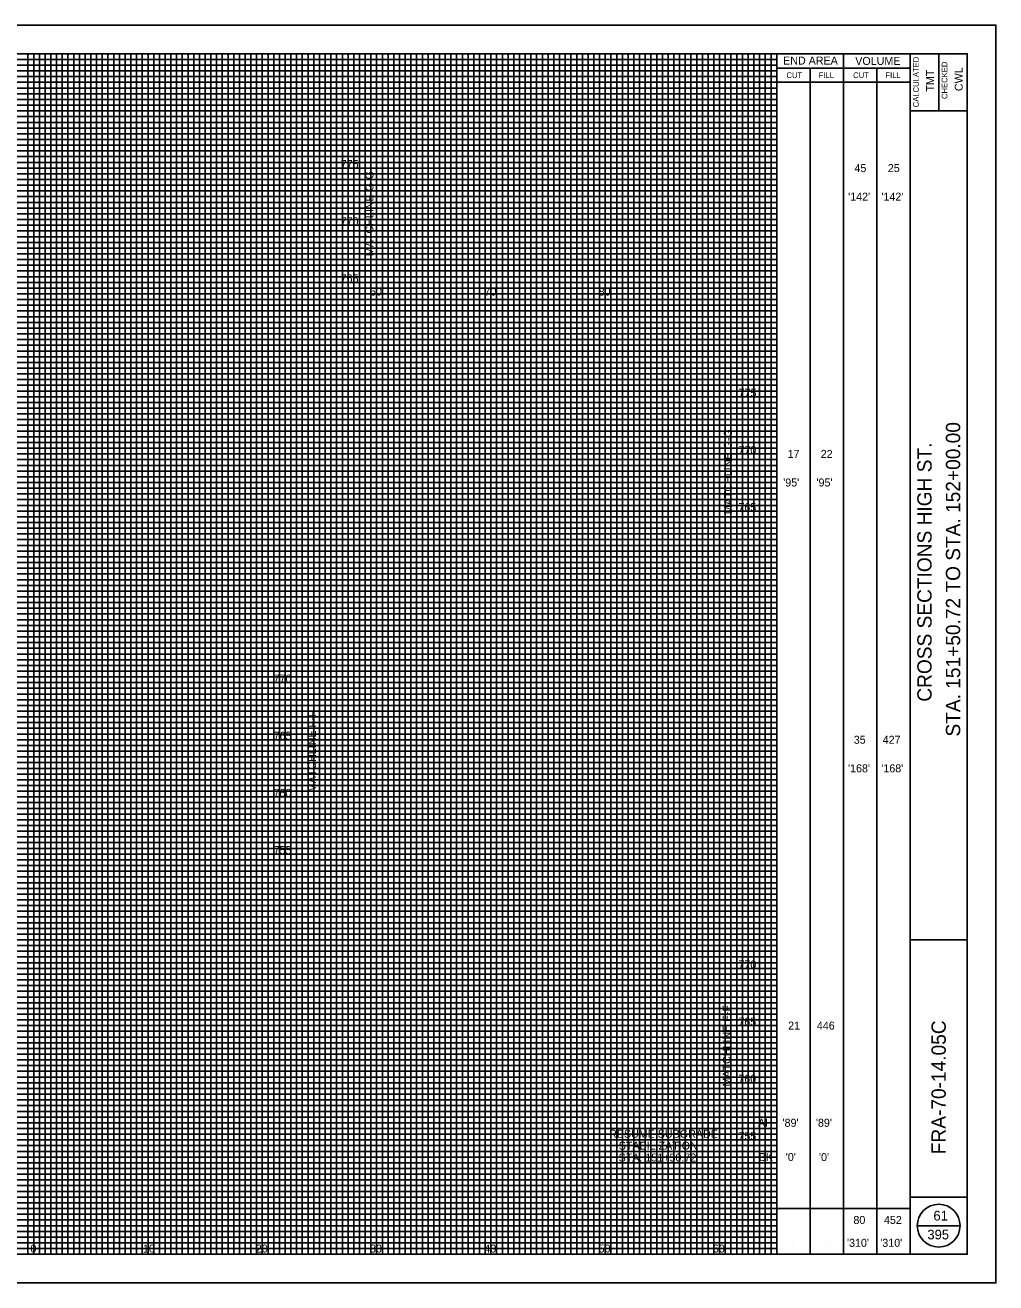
# Model space of a CAD drawing. Extents: x -10 to 160, y -2 to 568.
# Drawn here: x 75.1 to 160, y 342.5 to 452.5 of the extents above; entities that cross this region are included whole.
import ezdxf

# ---------------------------------------------------------------- set-up
doc = ezdxf.new("R2010")
doc.units = 0
for name, color, linetype in [('DR_P_Text', 7, 'Continuous'), ('SV_X_Text_Comment', 7, 'Continuous'), ('SV_X_Text_Elevation', 7, 'Continuous'), ('XS_P_Annotation', 7, 'Continuous'), ('XS_P_Finished_Grade', 7, 'Continuous'), ('XS_P_Subgrade', 7, 'Continuous'), ('XS_P_Text_MarkedPoint', 7, 'Continuous')]:
    doc.layers.add(name, color=color, linetype=linetype)

msp = doc.modelspace()

# ---------------------------------------------------------------- linework, layer by layer
at = {"layer": 'SV_X_Text_Comment'}
msp.add_lwpolyline([(-10, 342.5), (160, 342.5), (160, 452.5), (-10, 452.5)], close=True, dxfattribs=at)
at = {"layer": 'SV_X_Text_Elevation'}
for p, q in [((75.33, 345), (75.33, 450)), ((76.33, 345), (76.33, 450)), ((76.83, 345), (76.83, 450)), ((77.33, 345), (77.33, 450)), ((77.83, 345), (77.83, 450)), ((78.33, 345), (78.33, 450)), ((78.83, 345), (78.83, 450)), ((79.33, 345), (79.33, 450)), ((79.83, 345), (79.83, 450)), ((80.33, 345), (80.33, 450)), ((81.33, 345), (81.33, 450)), ((81.83, 345), (81.83, 450)), ((82.33, 345), (82.33, 450)), ((82.83, 345), (82.83, 450)), ((83.33, 345), (83.33, 450)), ((83.83, 345), (83.83, 450)), ((84.33, 345), (84.33, 450)), ((84.83, 345), (84.83, 450)), ((85.33, 345), (85.33, 450)), ((86.33, 345), (86.33, 450)), ((86.83, 345), (86.83, 450)), ((87.33, 345), (87.33, 450)), ((87.83, 345), (87.83, 450)), ((88.33, 345), (88.33, 450)), ((88.83, 345), (88.83, 450)), ((89.33, 345), (89.33, 450)), ((89.83, 345), (89.83, 450)), ((90.33, 345), (90.33, 450)), ((91.33, 345), (91.33, 450)), ((91.83, 345), (91.83, 450)), ((92.33, 345), (92.33, 450)), ((92.83, 345), (92.83, 450)), ((93.33, 345), (93.33, 450)), ((93.83, 345), (93.83, 450)), ((94.33, 345), (94.33, 450)), ((94.83, 345), (94.83, 450)), ((95.33, 345), (95.33, 450)), ((96.33, 345), (96.33, 450)), ((96.83, 345), (96.83, 450)), ((97.33, 345), (97.33, 450)), ((97.83, 345), (97.83, 450)), ((98.33, 345), (98.33, 450)), ((98.83, 345), (98.83, 450)), ((99.33, 345), (99.33, 450)), ((99.83, 345), (99.83, 450)), ((100.33, 345), (100.33, 450)), ((101.33, 345), (101.33, 450)), ((101.83, 345), (101.83, 450)), ((102.33, 345), (102.33, 450)), ((102.83, 345), (102.83, 450)), ((103.33, 345), (103.33, 450)), ((103.83, 345), (103.83, 450)), ((104.33, 345), (104.33, 450)), ((104.83, 345), (104.83, 450)), ((105.33, 345), (105.33, 450)), ((106.33, 345), (106.33, 450)), ((106.83, 345), (106.83, 450)), ((107.33, 345), (107.33, 450)), ((107.83, 345), (107.83, 450)), ((108.33, 345), (108.33, 450)), ((108.83, 345), (108.83, 450)), ((109.33, 345), (109.33, 450)), ((109.83, 345), (109.83, 450)), ((110.33, 345), (110.33, 450)), ((111.33, 345), (111.33, 450)), ((111.83, 345), (111.83, 450)), ((112.33, 345), (112.33, 450)), ((112.83, 345), (112.83, 450)), ((113.33, 345), (113.33, 450)), ((113.83, 345), (113.83, 450)), ((114.33, 345), (114.33, 450)), ((114.83, 345), (114.83, 450)), ((115.33, 345), (115.33, 450)), ((116.33, 345), (116.33, 450)), ((116.83, 345), (116.83, 450)), ((117.33, 345), (117.33, 450)), ((117.83, 345), (117.83, 450)), ((118.33, 345), (118.33, 450)), ((118.83, 345), (118.83, 450)), ((119.33, 345), (119.33, 450)), ((119.83, 345), (119.83, 450)), ((120.33, 345), (120.33, 450)), ((121.33, 345), (121.33, 450)), ((121.83, 345), (121.83, 450)), ((122.33, 345), (122.33, 450)), ((122.83, 345), (122.83, 450)), ((123.33, 345), (123.33, 450)), ((123.83, 345), (123.83, 450)), ((124.33, 345), (124.33, 450)), ((124.83, 345), (124.83, 450)), ((125.33, 345), (125.33, 450)), ((126.33, 345), (126.33, 450)), ((126.83, 345), (126.83, 450)), ((127.33, 345), (127.33, 450)), ((127.83, 345), (127.83, 450)), ((128.33, 345), (128.33, 450)), ((128.83, 345), (128.83, 450)), ((129.33, 345), (129.33, 450)), ((129.83, 345), (129.83, 450)), ((130.33, 345), (130.33, 450)), ((131.33, 345), (131.33, 450)), ((131.83, 345), (131.83, 450)), ((132.33, 345), (132.33, 450)), ((132.83, 345), (132.83, 450)), ((133.33, 345), (133.33, 450)), ((133.83, 345), (133.83, 450)), ((134.33, 345), (134.33, 450)), ((134.83, 345), (134.83, 450)), ((135.33, 345), (135.33, 450)), ((136.33, 345), (136.33, 450)), ((136.83, 345), (136.83, 450)), ((137.33, 345), (137.33, 450)), ((137.83, 345), (137.83, 450)), ((138.33, 345), (138.33, 450)), ((138.83, 345), (138.83, 450)), ((139.33, 345), (139.33, 450)), ((139.83, 345), (139.83, 450)), ((140.33, 345), (140.33, 450)), ((5.83, 449.5), (140.83, 449.5)), ((5.83, 449), (140.83, 449)), ((5.83, 448.5), (140.83, 448.5)), ((5.83, 448), (140.83, 448)), ((5.83, 447.5), (140.83, 447.5)), ((5.83, 447), (140.83, 447)), ((5.83, 446.5), (140.83, 446.5)), ((5.83, 446), (140.83, 446)), ((5.83, 445.5), (140.83, 445.5)), ((5.83, 444.5), (140.83, 444.5)), ((5.83, 444), (140.83, 444)), ((5.83, 443.5), (140.83, 443.5)), ((5.83, 443), (140.83, 443)), ((5.83, 442.5), (140.83, 442.5)), ((5.83, 442), (140.83, 442)), ((5.83, 441.5), (140.83, 441.5)), ((5.83, 441), (140.83, 441)), ((5.83, 440.5), (140.83, 440.5)), ((5.83, 439.5), (140.83, 439.5)), ((5.83, 439), (140.83, 439)), ((5.83, 438.5), (140.83, 438.5)), ((5.83, 438), (140.83, 438)), ((5.83, 437.5), (140.83, 437.5)), ((5.83, 437), (140.83, 437)), ((5.83, 436.5), (140.83, 436.5)), ((5.83, 436), (140.83, 436)), ((5.83, 435.5), (140.83, 435.5)), ((5.83, 434.5), (140.83, 434.5)), ((5.83, 434), (140.83, 434)), ((5.83, 433.5), (140.83, 433.5)), ((5.83, 433), (140.83, 433)), ((5.83, 432.5), (140.83, 432.5)), ((5.83, 432), (140.83, 432)), ((5.83, 431.5), (140.83, 431.5)), ((5.83, 431), (140.83, 431)), ((5.83, 430.5), (140.83, 430.5)), ((5.83, 429.5), (140.83, 429.5)), ((5.83, 429), (140.83, 429)), ((5.83, 428.5), (140.83, 428.5)), ((5.83, 428), (140.83, 428)), ((5.83, 427.5), (140.83, 427.5)), ((5.83, 427), (140.83, 427)), ((5.83, 426.5), (140.83, 426.5)), ((5.83, 426), (140.83, 426)), ((5.83, 425.5), (140.83, 425.5)), ((5.83, 424.5), (140.83, 424.5)), ((5.83, 424), (140.83, 424)), ((5.83, 423.5), (140.83, 423.5)), ((5.83, 423), (140.83, 423)), ((5.83, 422.5), (140.83, 422.5)), ((5.83, 422), (140.83, 422)), ((5.83, 421.5), (140.83, 421.5)), ((5.83, 421), (140.83, 421)), ((5.83, 420.5), (140.83, 420.5)), ((5.83, 419.5), (140.83, 419.5)), ((5.83, 419), (140.83, 419)), ((5.83, 418.5), (140.83, 418.5)), ((5.83, 418), (140.83, 418)), ((5.83, 417.5), (140.83, 417.5)), ((5.83, 417), (140.83, 417)), ((5.83, 416.5), (140.83, 416.5)), ((5.83, 416), (140.83, 416)), ((5.83, 415.5), (140.83, 415.5)), ((5.83, 414.5), (140.83, 414.5)), ((5.83, 414), (140.83, 414)), ((5.83, 413.5), (140.83, 413.5)), ((5.83, 413), (140.83, 413)), ((5.83, 412.5), (140.83, 412.5)), ((5.83, 412), (140.83, 412)), ((5.83, 411.5), (140.83, 411.5)), ((5.83, 411), (140.83, 411)), ((5.83, 410.5), (140.83, 410.5)), ((5.83, 409.5), (140.83, 409.5)), ((5.83, 409), (140.83, 409)), ((5.83, 408.5), (140.83, 408.5)), ((5.83, 408), (140.83, 408)), ((5.83, 407.5), (140.83, 407.5)), ((5.83, 407), (140.83, 407)), ((5.83, 406.5), (140.83, 406.5)), ((5.83, 406), (140.83, 406)), ((5.83, 405.5), (140.83, 405.5)), ((5.83, 404.5), (140.83, 404.5)), ((5.83, 404), (140.83, 404)), ((5.83, 403.5), (140.83, 403.5)), ((5.83, 403), (140.83, 403)), ((5.83, 402.5), (140.83, 402.5)), ((5.83, 402), (140.83, 402)), ((5.83, 401.5), (140.83, 401.5)), ((5.83, 401), (140.83, 401)), ((5.83, 400.5), (140.83, 400.5)), ((5.83, 399.5), (140.83, 399.5)), ((5.83, 399), (140.83, 399)), ((5.83, 398.5), (140.83, 398.5)), ((5.83, 398), (140.83, 398)), ((5.83, 397.5), (140.83, 397.5)), ((5.83, 397), (140.83, 397)), ((5.83, 396.5), (140.83, 396.5)), ((5.83, 396), (140.83, 396)), ((5.83, 395.5), (140.83, 395.5)), ((5.83, 394.5), (140.83, 394.5)), ((5.83, 394), (140.83, 394)), ((5.83, 393.5), (140.83, 393.5)), ((5.83, 393), (140.83, 393)), ((5.83, 392.5), (140.83, 392.5)), ((5.83, 392), (140.83, 392)), ((5.83, 391.5), (140.83, 391.5)), ((5.83, 391), (140.83, 391)), ((5.83, 390.5), (140.83, 390.5)), ((5.83, 389.5), (140.83, 389.5)), ((5.83, 389), (140.83, 389)), ((5.83, 388.5), (140.83, 388.5)), ((5.83, 388), (140.83, 388)), ((5.83, 387.5), (140.83, 387.5)), ((5.83, 387), (140.83, 387)), ((5.83, 386.5), (140.83, 386.5)), ((5.83, 386), (140.83, 386)), ((5.83, 385.5), (140.83, 385.5)), ((5.83, 384.5), (140.83, 384.5)), ((5.83, 384), (140.83, 384)), ((5.83, 383.5), (140.83, 383.5)), ((5.83, 383), (140.83, 383)), ((5.83, 382.5), (140.83, 382.5)), ((5.83, 382), (140.83, 382)), ((5.83, 381.5), (140.83, 381.5)), ((5.83, 381), (140.83, 381)), ((5.83, 380.5), (140.83, 380.5)), ((5.83, 379.5), (140.83, 379.5)), ((5.83, 379), (140.83, 379)), ((5.83, 378.5), (140.83, 378.5)), ((5.83, 378), (140.83, 378)), ((5.83, 377.5), (140.83, 377.5)), ((5.83, 377), (140.83, 377)), ((5.83, 376.5), (140.83, 376.5)), ((5.83, 376), (140.83, 376)), ((5.83, 375.5), (140.83, 375.5)), ((5.83, 374.5), (140.83, 374.5)), ((5.83, 374), (140.83, 374)), ((5.83, 373.5), (140.83, 373.5)), ((5.83, 373), (140.83, 373)), ((5.83, 372.5), (140.83, 372.5)), ((5.83, 372), (140.83, 372)), ((5.83, 371.5), (140.83, 371.5)), ((5.83, 371), (140.83, 371)), ((5.83, 370.5), (140.83, 370.5)), ((5.83, 369.5), (140.83, 369.5)), ((5.83, 369), (140.83, 369)), ((5.83, 368.5), (140.83, 368.5)), ((5.83, 368), (140.83, 368)), ((5.83, 367.5), (140.83, 367.5)), ((5.83, 367), (140.83, 367)), ((5.83, 366.5), (140.83, 366.5)), ((5.83, 366), (140.83, 366)), ((5.83, 365.5), (140.83, 365.5)), ((5.83, 364.5), (140.83, 364.5)), ((5.83, 364), (140.83, 364)), ((5.83, 363.5), (140.83, 363.5)), ((5.83, 363), (140.83, 363)), ((5.83, 362.5), (140.83, 362.5)), ((5.83, 362), (140.83, 362)), ((5.83, 361.5), (140.83, 361.5)), ((5.83, 361), (140.83, 361)), ((5.83, 360.5), (140.83, 360.5)), ((5.83, 359.5), (140.83, 359.5)), ((5.83, 359), (140.83, 359)), ((5.83, 358.5), (140.83, 358.5)), ((5.83, 358), (140.83, 358)), ((5.83, 357.5), (140.83, 357.5)), ((5.83, 357), (140.83, 357)), ((5.83, 356.5), (140.83, 356.5)), ((5.83, 356), (140.83, 356)), ((5.83, 355.5), (140.83, 355.5)), ((5.83, 354.5), (140.83, 354.5)), ((5.83, 354), (140.83, 354)), ((5.83, 353.5), (140.83, 353.5)), ((5.83, 353), (140.83, 353)), ((5.83, 352.5), (140.83, 352.5)), ((5.83, 352), (140.83, 352)), ((5.83, 351.5), (140.83, 351.5)), ((5.83, 351), (140.83, 351)), ((5.83, 350.5), (140.83, 350.5)), ((5.83, 349.5), (140.83, 349.5)), ((5.83, 349), (140.83, 349)), ((5.83, 348.5), (140.83, 348.5)), ((5.83, 348), (140.83, 348)), ((5.83, 347.5), (140.83, 347.5)), ((5.83, 347), (140.83, 347)), ((5.83, 346.5), (140.83, 346.5)), ((5.83, 346), (140.83, 346)), ((5.83, 345.5), (140.83, 345.5))]:
    msp.add_line(p, q, dxfattribs=at)
at = {"layer": 'XS_P_Annotation'}
for p, q in [((152.5, 345), (152.5, 450)), ((155, 450), (155, 445)), ((152.5, 445), (157.5, 445)), ((152.5, 372.5), (157.5, 372.5)), ((152.5, 350), (157.5, 350))]:
    msp.add_line(p, q, dxfattribs=at)
msp.add_lwpolyline([(0, 450), (157.5, 450), (157.5, 345), (0, 345)], close=True, dxfattribs=at)
at = {"layer": 'XS_P_Finished_Grade'}
for p, q in [((140.83, 345), (140.83, 450)), ((146.67, 345), (146.67, 450)), ((140.83, 448.75), (152.5, 448.75)), ((143.75, 345), (143.75, 448.75)), ((149.58, 345), (149.58, 448.75)), ((140.83, 447.5), (152.5, 447.5)), ((140.83, 349), (152.5, 349)), ((153.12, 347.5), (156.88, 347.5)), ((142.29, 346), (142.29, 346)), ((145.21, 346), (145.21, 346)), ((148.12, 346), (148.12, 346)), ((151.04, 346), (151.04, 346))]:
    msp.add_line(p, q, dxfattribs=at)
msp.add_circle((155, 347.5), 1.87, dxfattribs=at)
at = {"layer": 'XS_P_Subgrade'}
for p, q in [((105.83, 430.21), (105.83, 441.9)), ((135.83, 407.64), (135.83, 419.33)), ((100.83, 379.54), (100.83, 398.69)), ((135.83, 353.79), (135.83, 372.94))]:
    msp.add_line(p, q, dxfattribs=at)
at = {"layer": 'XS_P_Text_MarkedPoint'}
for p, q in [((75.83, 345), (75.83, 450)), ((80.83, 345), (80.83, 450)), ((85.83, 345), (85.83, 450)), ((90.83, 345), (90.83, 450)), ((95.83, 345), (95.83, 450)), ((100.83, 345), (100.83, 450)), ((105.83, 345), (105.83, 450)), ((110.83, 345), (110.83, 450)), ((115.83, 345), (115.83, 450)), ((120.83, 345), (120.83, 450)), ((125.83, 345), (125.83, 450)), ((130.83, 345), (130.83, 450)), ((135.83, 345), (135.83, 450)), ((5.83, 445), (140.83, 445)), ((5.83, 440), (140.83, 440)), ((5.83, 435), (140.83, 435)), ((5.83, 430), (140.83, 430)), ((5.83, 425), (140.83, 425)), ((5.83, 420), (140.83, 420)), ((5.83, 415), (140.83, 415)), ((5.83, 410), (140.83, 410)), ((5.83, 405), (140.83, 405)), ((5.83, 400), (140.83, 400)), ((5.83, 395), (140.83, 395)), ((5.83, 390), (140.83, 390)), ((5.83, 385), (140.83, 385)), ((5.83, 380), (140.83, 380)), ((5.83, 375), (140.83, 375)), ((5.83, 370), (140.83, 370)), ((5.83, 365), (140.83, 365)), ((5.83, 360), (140.83, 360)), ((5.83, 355), (140.83, 355)), ((5.83, 350), (140.83, 350))]:
    msp.add_line(p, q, dxfattribs=at)

# ---------------------------------------------------------------- texts
at = {"layer": 'DR_P_Text'}
for s, p in [('775', (102.69, 440)), ('45', (147.63, 439.65)), ('25', (150.55, 439.65)), ("'142'", (147.08, 437.15)), ("'142'", (149.99, 437.15)), ('770', (102.68, 435)), ('765', (102.68, 430)), ('60', (105.25, 428.85)), ('70', (115.26, 428.85)), ('80', (125.25, 428.85)), ('775', (137.49, 420)), ('770', (137.48, 415)), ('17', (141.78, 414.65)), ('22', (144.68, 414.65)), ("'95'", (141.4, 412.15)), ("'95'", (144.31, 412.15)), ('765', (137.48, 410)), ('770', (96.82, 395)), ('765', (96.82, 390)), ('35', (147.57, 389.65)), ('427', (150.1, 389.65)), ("'168'", (147.07, 387.15)), ("'168'", (149.98, 387.15)), ('760', (96.81, 385)), ('755', (96.82, 380)), ('770', (137.48, 370)), ('765', (137.48, 365)), ('21', (141.83, 364.65)), ('446', (144.34, 364.65)), ('760', (137.47, 360)), ('AH', (139.19, 356.15)), ("'89'", (141.34, 356.15)), ("'89'", (144.26, 356.15)), ('755', (137.48, 355)), ('BK', (139.26, 353.15)), ("'0'", (141.62, 353.15)), ("'0'", (144.53, 353.15)), ('80', (147.54, 347.65)), ('452', (150.21, 347.65)), ('0', (75.55, 345.15)), ('0', (75.55, 345.15)), ('10', (85.39, 345.15)), ('20', (95.26, 345.15)), ('30', (105.25, 345.15)), ('40', (115.25, 345.15)), ('50', (125.25, 345.15)), ('60', (135.25, 345.15)), ("'310'", (146.98, 345.65)), ("'310'", (149.89, 345.65))]:
    msp.add_text(s, height=0.7, dxfattribs=at).set_placement(p)
at = {"layer": 'XS_P_Finished_Grade'}
for s, height, p in [('END AREA', 0.7, (141.39, 449.05)), ('VOLUME', 0.7, (147.7, 449.02)), ('CUT', 0.5, (141.68, 447.87)), ('FILL', 0.5, (144.5, 447.87)), ('CUT', 0.5, (147.52, 447.87)), ('FILL', 0.5, (150.34, 447.87)), ('61', 0.85, (154.54, 347.95)), ('395', 0.85, (154.01, 346.3))]:
    msp.add_text(s, height=height, dxfattribs=at).set_placement(p)
for s, height, p in [('CALCULATED', 0.5, (153.26, 445.32)), ('CHECKED', 0.5, (155.76, 446.04)), ('TMT', 0.7, (154.6, 446.69)), ('CWL', 0.7, (157.1, 446.73)), ('STA. 151+50.72 TO STA. 152+00.00', 1.25, (156.88, 390.28)), ('CROSS SECTIONS HIGH ST.', 1.25, (154.38, 393.33)), ('FRA-70-14.05C', 1.25, (155.62, 353.75))]:
    msp.add_text(s, height=height, rotation=90, dxfattribs=at).set_placement(p)
at = {"layer": 'XS_P_Subgrade'}
for s, p in [('MATCHLINE G-G', (105.55, 432.3)), ('MATCHLINE G-G', (136.91, 409.73)), ('MATCHLINE F-F', (100.53, 385.41)), ('MATCHLINE F-F', (136.81, 359.67))]:
    msp.add_text(s, height=0.7, rotation=90, dxfattribs=at).set_placement(p)
for s, p in [('RESUME SUBGRADE', (126.16, 355.19)), ('STABILIZATION', (127.01, 354.15)), ('STA. 151+50.72', (127, 353.11))]:
    msp.add_text(s, height=0.7, dxfattribs=at).set_placement(p)

doc.saveas('drawing.dxf')
